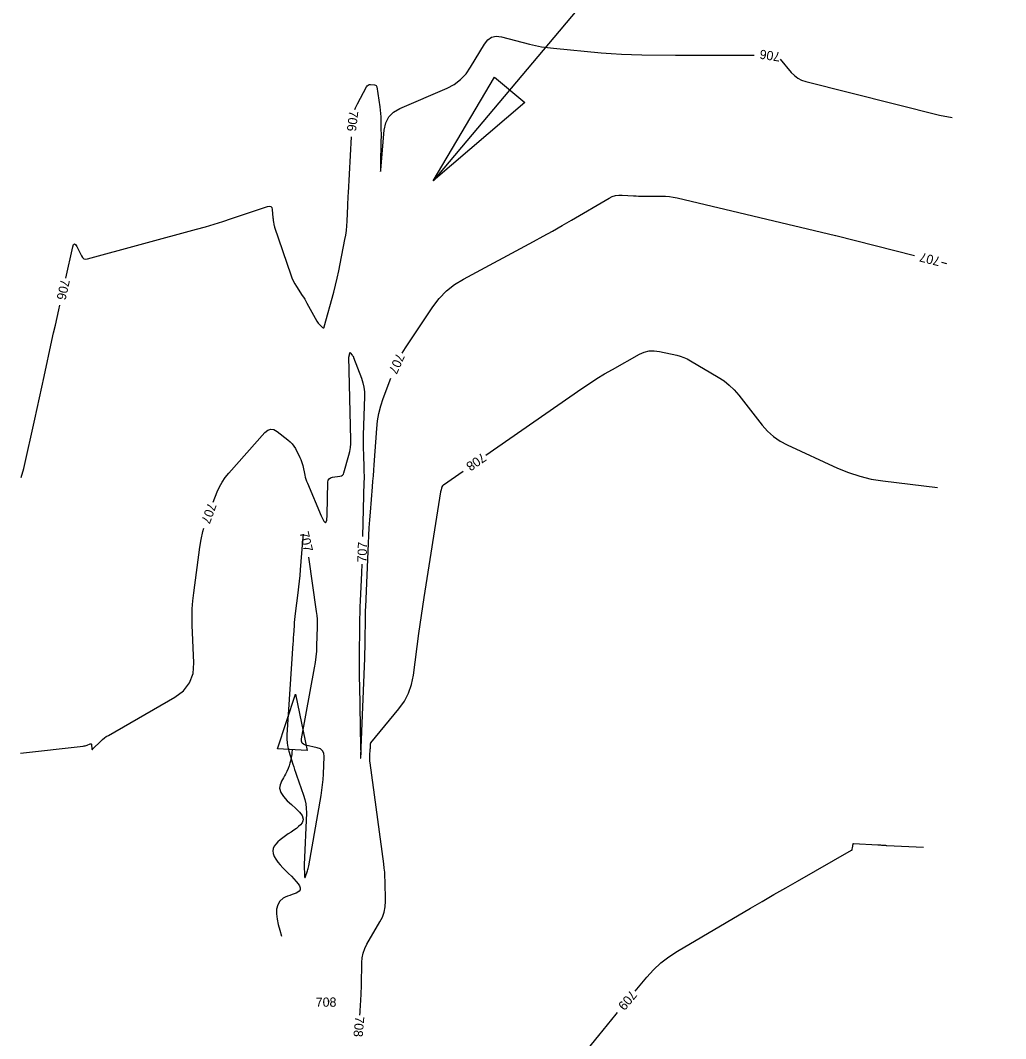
# Model space of a CAD drawing. Extents: x -468541894 to 3393103, y -306086142 to 1227927.
# Drawn here: x 1843038.3 to 1843465.2, y 539041.5 to 539482.8 of the extents above; entities that cross this region are included whole.
import ezdxf

# ---------------------------------------------------------------- set-up
doc = ezdxf.new("R2010")
doc.units = 0
for name, color, linetype in [('DT_X_Contour_Minor', 7, 'Continuous'), ('Level 19', 7, 'Continuous'), ('Level 40', 7, 'Continuous'), ('Level 56', 7, 'Continuous')]:
    doc.layers.add(name, color=color, linetype=linetype)

msp = doc.modelspace()

# ---------------------------------------------------------------- linework, layer by layer
at = {"layer": 'DT_X_Contour_Minor'}
for points in [[(1843183.19, 539444.11), (1843183.44, 539444.83), (1843184.3, 539446.66), (1843188.27, 539454.04), (1843188.57, 539454.47), (1843188.95, 539454.76), (1843189.4, 539454.92), (1843189.93, 539454.95), (1843191.77, 539454.81), (1843192.12, 539454.74), (1843192.39, 539454.57), (1843192.58, 539454.32), (1843192.68, 539453.97), (1843193.99, 539445.28), (1843194.18, 539443.87), (1843194.32, 539442.46), (1843194.41, 539441.04), (1843194.46, 539439.62), (1843194.53, 539434.96), (1843194.54, 539433.97), (1843194.54, 539432.97), (1843194.54, 539431.97), (1843194.52, 539430.98), (1843194.33, 539419.71), (1843194.32, 539417.9), (1843194.37, 539417.29), (1843194.48, 539417.89), (1843194.65, 539419.69), (1843195.93, 539435.26), (1843196.56, 539438.34), (1843197.88, 539440.93), (1843199.91, 539443), (1843202.63, 539444.58), (1843223.14, 539453.41), (1843226.25, 539455.04), (1843229, 539457.09), (1843231.37, 539459.55), (1843233.38, 539462.43), (1843239.35, 539472.52), (1843240.77, 539474.33), (1843242.48, 539475.45), (1843244.48, 539475.87), (1843246.77, 539475.59), (1843258.84, 539472.49), (1843261.43, 539471.88), (1843264.04, 539471.37), (1843266.68, 539470.97), (1843269.32, 539470.66), (1843289.87, 539468.73), (1843294.28, 539468.37), (1843298.69, 539468.1), (1843303.11, 539467.92), (1843307.53, 539467.84), (1843322.09, 539467.73), (1843325.22, 539467.71), (1843328.34, 539467.69), (1843331.46, 539467.68), (1843334.58, 539467.68), (1843356.17, 539467.66)], [(1843367.49, 539465.96), (1843372.32, 539460.23), (1843373.66, 539458.87), (1843375.15, 539457.76), (1843376.8, 539456.9), (1843378.62, 539456.29), (1843436.57, 539441.68), (1843442.03, 539440.7)], [(1843057.96, 539371.04), (1843060.96, 539384.58), (1843061.29, 539385.61), (1843061.71, 539385.99), (1843062.19, 539385.71), (1843062.75, 539384.78), (1843064.71, 539380.68), (1843065.19, 539379.94), (1843065.81, 539379.49), (1843066.55, 539379.32), (1843067.43, 539379.43), (1843114.64, 539392.25), (1843118.44, 539393.31), (1843122.23, 539394.43), (1843125.99, 539395.61), (1843129.74, 539396.84), (1843145.38, 539402.12), (1843146.19, 539402.27), (1843146.79, 539402.1), (1843147.19, 539401.62), (1843147.38, 539400.82), (1843147.73, 539397.17), (1843147.77, 539396.77), (1843147.82, 539396.36), (1843147.88, 539395.95), (1843147.94, 539395.55), (1843148.15, 539394.23), (1843148.21, 539393.95), (1843148.27, 539393.67), (1843148.35, 539393.39), (1843148.43, 539393.12), (1843155.46, 539372.51), (1843155.95, 539371.19), (1843156.53, 539369.91), (1843157.18, 539368.67), (1843157.92, 539367.47), (1843160.44, 539363.61), (1843160.97, 539362.78), (1843161.49, 539361.93), (1843161.99, 539361.08), (1843162.47, 539360.22), (1843166.72, 539352.48), (1843166.99, 539352.03), (1843167.29, 539351.61), (1843167.62, 539351.22), (1843167.99, 539350.85), (1843169.25, 539349.69), (1843169.5, 539349.52), (1843169.71, 539349.5), (1843169.87, 539349.63), (1843169.98, 539349.9), (1843174.04, 539364.95), (1843174.84, 539368.01), (1843175.58, 539371.08), (1843176.26, 539374.16), (1843176.89, 539377.26), (1843178.92, 539387.76), (1843179.26, 539389.76), (1843179.54, 539391.76), (1843179.74, 539393.77), (1843179.87, 539395.78), (1843180.17, 539402.39), (1843180.23, 539403.81), (1843180.3, 539405.22), (1843180.38, 539406.64), (1843180.45, 539408.05), (1843181.78, 539432.25)], [(1843203.73, 539338.62), (1843205.1, 539340.82), (1843217, 539358.69), (1843219.74, 539362.31), (1843222.85, 539365.51), (1843226.34, 539368.31), (1843230.21, 539370.68), (1843260.63, 539386.97), (1843264.77, 539389.21), (1843268.89, 539391.49), (1843272.99, 539393.81), (1843277.06, 539396.17), (1843293.42, 539405.74), (1843294.75, 539406.39), (1843296.14, 539406.84), (1843297.57, 539407.06), (1843299.06, 539407.07), (1843304, 539406.74), (1843305.06, 539406.68), (1843306.12, 539406.63), (1843307.18, 539406.6), (1843308.24, 539406.6), (1843316.13, 539406.59), (1843317.81, 539406.54), (1843319.48, 539406.39), (1843321.14, 539406.15), (1843322.79, 539405.81), (1843391.52, 539389.55), (1843391.52, 539389.55), (1843391.53, 539389.54), (1843391.53, 539389.54), (1843391.53, 539389.54), (1843391.54, 539389.53), (1843391.54, 539389.53), (1843391.55, 539389.52), (1843391.55, 539389.52), (1843391.55, 539389.52), (1843425.76, 539380.89)], [(1843437.4, 539377.96), (1843439.54, 539377.42)], [(1843038.61, 539284.71), (1843039.79, 539288.5), (1843044.52, 539310.01), (1843045.53, 539314.61), (1843046.54, 539319.22), (1843047.56, 539323.83), (1843048.57, 539328.44), (1843051.98, 539343.97), (1843052.71, 539347.3), (1843053.45, 539350.63), (1843054.18, 539353.96), (1843054.92, 539357.29), (1843055.37, 539359.32)], [(1843121.88, 539273.98), (1843123.59, 539278.39), (1843124.57, 539280.6), (1843125.73, 539282.7), (1843127.07, 539284.69), (1843128.6, 539286.57), (1843144.23, 539304.18), (1843145.47, 539305.23), (1843146.76, 539305.66), (1843148.12, 539305.47), (1843149.53, 539304.67), (1843154.23, 539301.01), (1843155.18, 539300.18), (1843156.04, 539299.27), (1843156.78, 539298.26), (1843157.43, 539297.18), (1843159.43, 539293.35), (1843159.83, 539292.52), (1843160.16, 539291.67), (1843160.44, 539290.8), (1843160.66, 539289.9), (1843161.54, 539285.71), (1843161.75, 539284.82), (1843162, 539283.94), (1843162.3, 539283.07), (1843162.63, 539282.22), (1843168.59, 539267.99), (1843169.72, 539265.73), (1843170.54, 539265.07), (1843171.05, 539265.99), (1843171.26, 539268.5), (1843171.5, 539282.58), (1843171.64, 539283.47), (1843172.02, 539284.14), (1843172.64, 539284.59), (1843173.51, 539284.83), (1843176.74, 539285.24), (1843177.37, 539285.4), (1843177.87, 539285.71), (1843178.25, 539286.16), (1843178.5, 539286.76), (1843180.64, 539294.37), (1843181.03, 539296.01), (1843181.3, 539297.66), (1843181.45, 539299.33), (1843181.48, 539301.01), (1843180.67, 539336.91), (1843180.67, 539337.03), (1843180.68, 539337.15), (1843180.7, 539337.27), (1843180.73, 539337.39), (1843180.83, 539337.77), (1843180.85, 539337.85), (1843180.87, 539337.93), (1843180.89, 539338.02), (1843180.9, 539338.1), (1843181.01, 539338.64), (1843181.04, 539338.73), (1843181.08, 539338.77), (1843181.14, 539338.76), (1843181.21, 539338.7), (1843182.08, 539337.68), (1843182.26, 539337.45), (1843182.42, 539337.22), (1843182.55, 539336.97), (1843182.66, 539336.7), (1843186.06, 539327.71), (1843186.69, 539325.76), (1843187.12, 539323.78), (1843187.35, 539321.77), (1843187.39, 539319.73), (1843186.88, 539303.07), (1843186.84, 539301.05), (1843186.83, 539299.03), (1843186.85, 539297.01), (1843186.9, 539294.99), (1843187.12, 539288.4), (1843187.16, 539286.99), (1843187.18, 539285.57), (1843187.18, 539284.16), (1843187.15, 539282.75), (1843186.59, 539259.14)], [(1843239.98, 539294.29), (1843281.6, 539323.28), (1843284.82, 539325.47), (1843288.09, 539327.56), (1843291.41, 539329.58), (1843294.78, 539331.51), (1843306.55, 539338.07), (1843308.62, 539339), (1843310.75, 539339.52), (1843312.94, 539339.63), (1843315.2, 539339.32), (1843322.65, 539337.66), (1843324.22, 539337.25), (1843325.75, 539336.71), (1843327.23, 539336.06), (1843328.66, 539335.28), (1843340.67, 539328.17), (1843343.15, 539326.54), (1843345.45, 539324.71), (1843347.57, 539322.67), (1843349.51, 539320.42), (1843359.72, 539307.38), (1843362.04, 539304.75), (1843364.62, 539302.44), (1843367.45, 539300.47), (1843370.54, 539298.82), (1843392.37, 539288.76), (1843397.1, 539286.79), (1843401.94, 539285.21), (1843406.88, 539284.01), (1843411.94, 539283.19), (1843435.72, 539280.27)], [(1843186.22, 539247.15), (1843186.22, 539247.06), (1843186.06, 539243.35), (1843185.52, 539231.23), (1843185.41, 539228.63), (1843185.33, 539226.03), (1843185.27, 539223.43), (1843185.23, 539220.83), (1843185.09, 539206.68), (1843185.07, 539203.65), (1843185.08, 539200.62), (1843185.11, 539197.59), (1843185.15, 539194.56), (1843185.69, 539167.77), (1843185.7, 539167.53), (1843185.7, 539167.3), (1843185.71, 539167.06), (1843185.71, 539166.82), (1843185.73, 539166.04), (1843185.73, 539165.87), (1843185.73, 539165.7), (1843185.73, 539165.54), (1843185.73, 539165.37), (1843185.71, 539163.43), (1843185.71, 539163.11), (1843185.72, 539163.01), (1843185.73, 539163.11), (1843185.75, 539163.42), (1843185.85, 539165.39), (1843185.86, 539165.61), (1843185.88, 539165.83), (1843185.89, 539166.04), (1843185.9, 539166.26), (1843185.94, 539166.98), (1843185.95, 539167.13), (1843185.96, 539167.28), (1843185.96, 539167.43), (1843185.97, 539167.59), (1843187.51, 539206.42), (1843187.59, 539208.63), (1843187.65, 539210.83), (1843187.7, 539213.04), (1843187.72, 539215.25), (1843187.78, 539222.46), (1843187.79, 539224.01), (1843187.83, 539225.55), (1843187.87, 539227.1), (1843187.93, 539228.64), (1843189.09, 539256.1), (1843189.26, 539259.49), (1843189.45, 539262.88), (1843189.68, 539266.26), (1843189.95, 539269.64), (1843190.87, 539280.68), (1843191.06, 539283.05), (1843191.24, 539285.41), (1843191.42, 539287.78), (1843191.59, 539290.15), (1843192.67, 539305.84), (1843193.02, 539309.18), (1843193.61, 539312.47), (1843194.44, 539315.7), (1843195.51, 539318.88), (1843198.83, 539327.69)], [(1843185.37, 539051.7), (1843185.47, 539052.92), (1843185.56, 539054.08), (1843185.64, 539055.25), (1843185.71, 539056.41), (1843185.77, 539057.58), (1843185.96, 539061.38), (1843186, 539062.2), (1843186.03, 539063.01), (1843186.05, 539063.83), (1843186.07, 539064.64), (1843186.23, 539074.5), (1843186.39, 539076.58), (1843186.81, 539078.58), (1843187.49, 539080.52), (1843188.43, 539082.38), (1843194.08, 539092.05), (1843195.14, 539094.17), (1843195.88, 539096.37), (1843196.31, 539098.64), (1843196.43, 539101.01), (1843196.3, 539109.8), (1843196.24, 539111.69), (1843196.13, 539113.57), (1843195.96, 539115.44), (1843195.73, 539117.31), (1843189.85, 539161.05), (1843189.77, 539161.77), (1843189.72, 539162.49), (1843189.71, 539163.22), (1843189.73, 539163.94), (1843189.91, 539167.11), (1843189.92, 539167.22), (1843189.92, 539167.33), (1843189.93, 539167.44), (1843189.93, 539167.55), (1843189.95, 539167.91), (1843189.95, 539167.98), (1843189.95, 539168.06), (1843189.95, 539168.13), (1843189.95, 539168.21), (1843189.96, 539169.03), (1843189.98, 539169.2), (1843190.02, 539169.36), (1843190.09, 539169.51), (1843190.19, 539169.65), (1843202.31, 539184.47), (1843204.65, 539187.76), (1843206.48, 539191.27), (1843207.79, 539195.01), (1843208.59, 539198.96), (1843210.98, 539217.12), (1843211.51, 539221.01), (1843212.06, 539224.9), (1843212.64, 539228.78), (1843213.24, 539232.66), (1843220.49, 539278.51), (1843220.53, 539278.73), (1843220.58, 539278.95), (1843220.62, 539279.16), (1843220.68, 539279.38), (1843220.87, 539280.08), (1843220.91, 539280.23), (1843220.96, 539280.38), (1843221.02, 539280.52), (1843221.08, 539280.66), (1843221.29, 539281.13), (1843221.34, 539281.22), (1843221.4, 539281.31), (1843221.47, 539281.39), (1843221.56, 539281.45), (1843230.14, 539287.43)], [(1843038.28, 539165.14), (1843038.37, 539165.15), (1843065.47, 539168.27), (1843065.91, 539168.34), (1843066.35, 539168.43), (1843066.78, 539168.56), (1843067.2, 539168.71), (1843068.57, 539169.25), (1843068.82, 539169.31), (1843069.01, 539169.26), (1843069.13, 539169.11), (1843069.17, 539168.85), (1843069.22, 539167.24), (1843069.26, 539166.96), (1843069.36, 539166.84), (1843069.52, 539166.86), (1843069.74, 539167.03), (1843073.15, 539170.44), (1843073.9, 539171.14), (1843074.7, 539171.79), (1843075.53, 539172.39), (1843076.41, 539172.93), (1843105.21, 539189.44), (1843108.98, 539192.24), (1843111.61, 539195.67), (1843113.11, 539199.73), (1843113.47, 539204.41), (1843112.78, 539220.73), (1843112.71, 539224.22), (1843112.79, 539227.71), (1843113.03, 539231.19), (1843113.41, 539234.67), (1843116.02, 539254.42), (1843116.58, 539257.84), (1843117.34, 539261.21), (1843117.78, 539262.71)], [(1843160.88, 539260.08), (1843160.86, 539260.04), (1843160.53, 539257.22), (1843159.52, 539244.66), (1843159.3, 539242.18), (1843159.06, 539239.7), (1843158.79, 539237.22), (1843158.48, 539234.74), (1843157.34, 539225.77), (1843157.18, 539224.48), (1843157.05, 539223.18), (1843156.94, 539221.89), (1843156.86, 539220.59), (1843156.61, 539216.34), (1843156.55, 539215.43), (1843156.5, 539214.52), (1843156.44, 539213.61), (1843156.38, 539212.71)], [(1843156.38, 539212.71), (1843153.72, 539173.16), (1843153.68, 539171.37), (1843153.81, 539169.6), (1843154.1, 539167.85), (1843154.56, 539166.13), (1843156.32, 539160.51), (1843156.7, 539159.31), (1843157.1, 539158.11), (1843157.51, 539156.91), (1843157.93, 539155.72), (1843161.02, 539147.06), (1843161.59, 539145.19), (1843161.98, 539143.29), (1843162.18, 539141.36), (1843162.2, 539139.4), (1843161.31, 539116.78), (1843161.3, 539116.09), (1843161.29, 539115.4), (1843161.3, 539114.71), (1843161.33, 539114.02), (1843161.44, 539111.76), (1843161.49, 539111.39), (1843161.56, 539111.26), (1843161.67, 539111.37), (1843161.81, 539111.71), (1843162.65, 539114.19), (1843162.82, 539114.73), (1843162.97, 539115.27), (1843163.1, 539115.82), (1843163.21, 539116.37), (1843168.56, 539146.87), (1843168.92, 539149.16), (1843169.21, 539151.46), (1843169.42, 539153.77), (1843169.56, 539156.08), (1843169.89, 539163.73), (1843169.75, 539165.16), (1843169.21, 539166.28), (1843168.27, 539167.09), (1843166.92, 539167.58), (1843161.85, 539168.7), (1843160.92, 539169.04), (1843160.32, 539169.6), (1843160.04, 539170.38), (1843160.08, 539171.36), (1843165.76, 539202.12), (1843166.16, 539204.53), (1843166.46, 539206.94), (1843166.67, 539209.37), (1843166.78, 539211.81), (1843167.01, 539219.8), (1843167.02, 539221.51), (1843166.96, 539223.21), (1843166.82, 539224.91), (1843166.62, 539226.61), (1843163.22, 539250.19)], [(1843304.63, 539062.02), (1843309.65, 539068.07), (1843312.61, 539071.35), (1843315.81, 539074.33), (1843319.27, 539077.01), (1843322.97, 539079.41), (1843354.68, 539098.04), (1843359.73, 539100.99), (1843364.8, 539103.93), (1843369.87, 539106.86), (1843374.95, 539109.77), (1843398.43, 539123.16), (1843398.54, 539123.24), (1843398.62, 539123.34), (1843398.68, 539123.45), (1843398.72, 539123.59), (1843398.82, 539124.18), (1843398.83, 539124.21), (1843398.83, 539124.24), (1843398.84, 539124.28), (1843398.84, 539124.31), (1843398.86, 539124.41), (1843398.86, 539124.44), (1843398.87, 539124.46), (1843398.87, 539124.48), (1843398.87, 539124.5), (1843398.91, 539124.69), (1843398.91, 539124.73), (1843398.92, 539124.77), (1843398.93, 539124.81), (1843398.93, 539124.85), (1843399.03, 539125.43), (1843399.04, 539125.49), (1843399.05, 539125.56), (1843399.06, 539125.63), (1843399.07, 539125.7), (1843399.11, 539125.92), (1843399.12, 539125.96), (1843399.15, 539125.99), (1843399.18, 539126), (1843399.22, 539126.01), (1843409.87, 539125.5), (1843410.25, 539125.48), (1843410.62, 539125.45), (1843410.99, 539125.43), (1843411.37, 539125.4), (1843412.58, 539125.31), (1843412.85, 539125.29), (1843413.11, 539125.27), (1843413.37, 539125.26), (1843413.63, 539125.24), (1843429.6, 539124.4)], [(1843171.7, 539057.32), (1843171.74, 539057.31), (1843171.75, 539057.31), (1843171.75, 539057.3), (1843171.76, 539057.3), (1843171.76, 539057.29), (1843171.76, 539057.18), (1843171.76, 539057.16), (1843171.76, 539057.15), (1843171.78, 539057.15), (1843171.79, 539057.16), (1843171.94, 539057.23), (1843171.96, 539057.25), (1843171.98, 539057.27), (1843171.99, 539057.3), (1843171.98, 539057.33), (1843171.89, 539057.79), (1843171.88, 539057.8), (1843171.88, 539057.81), (1843171.87, 539057.8), (1843171.86, 539057.79), (1843171.83, 539057.75), (1843171.82, 539057.74), (1843171.81, 539057.73), (1843171.81, 539057.72), (1843171.81, 539057.71), (1843171.69, 539057.34), (1843171.69, 539057.33), (1843171.69, 539057.33), (1843171.69, 539057.32), (1843171.7, 539057.32)], [(1843280.06, 539032.08), (1843288.85, 539042.89), (1843290.73, 539045.2), (1843292.63, 539047.51), (1843294.52, 539049.82), (1843296.43, 539052.12), (1843296.97, 539052.78)]]:
    msp.add_lwpolyline(points, dxfattribs=at)
at = {"layer": 'Level 40'}
for p, q in [((1843465.17, 539708.3), (1843217.11, 539413.21)), ((1843217.11, 539413.21), (1843243.73, 539458.2)), ((1843243.73, 539458.2), (1843256.88, 539447.15)), ((1843256.88, 539447.15), (1843217.11, 539413.21))]:
    msp.add_line(p, q, dxfattribs=at)
at = {"layer": 'Level 56'}
for p, q in [((1843149.64, 539167.14), (1843157.46, 539190.73)), ((1843157.46, 539190.73), (1843162.49, 539166.4)), ((1843162.49, 539166.4), (1843149.64, 539167.14))]:
    msp.add_line(p, q, dxfattribs=at)
msp.add_spline([(1843156, 539166.8), (1843155.95, 539165.85), (1843153.13, 539156.12), (1843150.6, 539150.01), (1843160.87, 539136.66), (1843147.67, 539122.86), (1843159.06, 539105.37), (1843152.17, 539102.36), (1843151.39, 539085.9)], degree=3, dxfattribs=at)

# ---------------------------------------------------------------- texts
at = {"layer": 'Level 19'}
for s, rotation, p in [('706', 171.4512, (1843367.78, 539468.84)), ('706', 263.1866, (1843180.76, 539443.81)), ('707', 165.8427, (1843437.18, 539380.07)), ('706', 257.5238, (1843055.87, 539370.86)), ('707', 245.8407, (1843201.34, 539338.91)), ('708', 214.8642, (1843238.36, 539295.6)), ('707', 250.0116, (1843119.62, 539274.04)), ('707', 283.3557, (1843159.2, 539260.8)), ('707', 88.2243, (1843188.27, 539247.81)), ('709', 230.3427, (1843302.69, 539062.81)), ('708', 265.2682, (1843183.33, 539051.28))]:
    msp.add_text(s, height=4, rotation=rotation, dxfattribs=at).set_placement(p)
msp.add_text('708', height=4, dxfattribs=at).set_placement((1843166.28, 539055.32))

doc.saveas('drawing.dxf')
